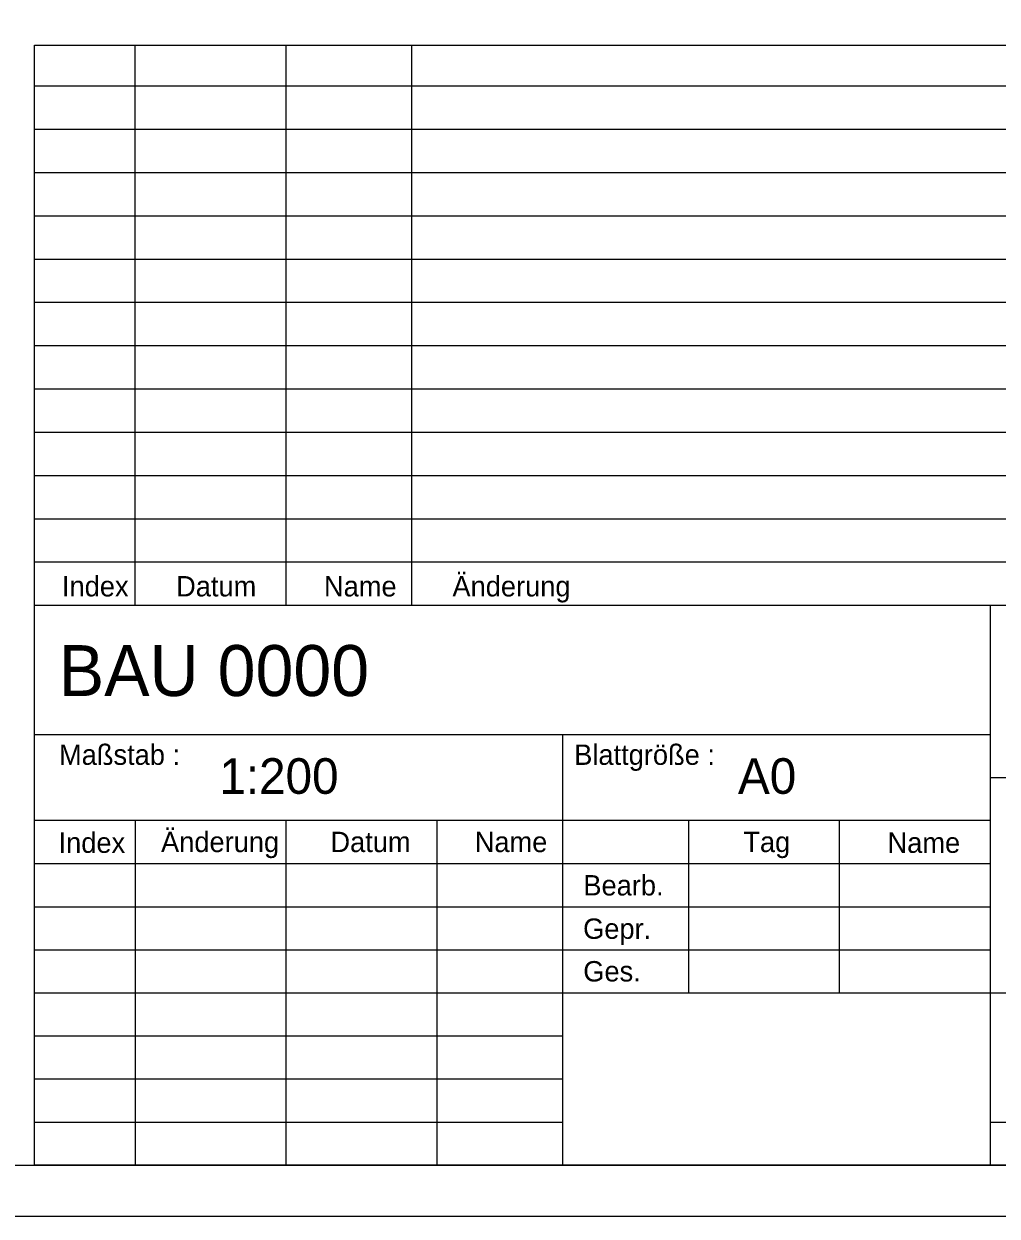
# Model space of a CAD drawing. Extents: x 0 to 238, y 0 to 168.
# Drawn here: x 201.01 to 220.13, y 0 to 23.42 of the extents above; entities that cross this region are included whole.
import ezdxf

# ---------------------------------------------------------------- set-up
doc = ezdxf.new("R2010")
doc.units = 0
doc.layers.add('90_Plankopf', color=7, linetype='Continuous')

msp = doc.modelspace()

# ---------------------------------------------------------------- linework, layer by layer
at = {"layer": '90_Plankopf'}
for p, q in [((201.224, 11.998), (201.224, 22.996)), ((201.224, 22.996), (236.8, 22.996)), ((203.2, 11.998), (203.2, 22.996)), ((206.165, 11.998), (206.165, 22.996)), ((208.636, 11.998), (208.636, 22.996)), ((201.224, 22.198), (236.8, 22.198)), ((201.224, 21.348), (236.8, 21.348)), ((201.224, 20.498), (236.8, 20.498)), ((201.224, 19.648), (236.8, 19.648)), ((201.224, 18.798), (236.8, 18.798)), ((201.224, 17.948), (236.8, 17.948)), ((201.224, 17.098), (236.8, 17.098)), ((201.224, 16.248), (236.8, 16.248)), ((201.224, 15.398), (236.8, 15.398)), ((201.224, 14.548), (236.8, 14.548)), ((201.224, 13.698), (236.8, 13.698)), ((201.224, 12.848), (236.8, 12.848)), ((201.224, 11.998), (236.8, 11.998)), ((201.224, 1), (201.224, 11.998)), ((201.224, 11.998), (236.8, 11.998)), ((220, 1), (220, 11.998)), ((201.224, 9.46), (220, 9.46)), ((211.6, 1), (211.6, 9.46)), ((220, 8.614), (236.8, 8.614)), ((201.224, 7.774), (220, 7.774)), ((203.2, 7.768), (203.2, 1)), ((206.165, 1), (206.165, 7.768)), ((209.13, 1), (209.13, 7.768)), ((214.071, 7.768), (214.071, 4.384)), ((217.036, 4.384), (217.036, 7.768)), ((201.224, 6.926), (220, 6.926)), ((201.224, 6.076), (220, 6.076)), ((201.224, 5.23), (220, 5.23)), ((201.224, 4.384), (220, 4.384)), ((201.224, 4.384), (220, 4.384)), ((211.6, 4.384), (220, 4.384)), ((220, 4.384), (236.8, 4.384)), ((211.6, 3.538), (201.224, 3.538)), ((211.6, 2.692), (201.224, 2.692)), ((201.224, 1.846), (211.6, 1.846)), ((220, 1.846), (236.8, 1.846)), ((236.8, 1), (201.224, 1)), ((201.224, 1), (211.6, 1)), ((203.56, 1), (236.8, 1)), ((203.56, 1), (236.8, 1))]:
    msp.add_line(p, q, dxfattribs=at)
for points in [[(0, 0), (237.8, 0), (237.8, 168.2), (0, 168.2)], [(5, 1), (236.8, 1), (236.8, 167.2), (5, 167.2)]]:
    msp.add_lwpolyline(points, close=True, dxfattribs=at)

# ---------------------------------------------------------------- texts
for s, height, p in [('Änderung', 0.4, (209.431, 12.171)), ('Index', 0.4, (201.761, 12.171)), ('Datum', 0.4, (204.003, 12.171)), ('Name', 0.4, (206.908, 12.171)), ('BAU 0000      ', 1, (201.698, 10.215)), ('Maßstab :', 0.4, (201.703, 8.863)), ('Blattgröße :', 0.39998, (211.823, 8.863)), ('1:200    ', 0.7, (204.852, 8.294)), ('A0       ', 0.7, (215.04, 8.294)), ('Index', 0.4, (201.694, 7.135)), ('Änderung', 0.4, (203.707, 7.15)), ('Datum', 0.4, (207.034, 7.15)), ('Name', 0.4, (209.869, 7.15)), ('Tag', 0.4, (215.145, 7.15)), ('Name', 0.4, (217.978, 7.135)), ('Bearb.', 0.4, (212.003, 6.298)), ('Gepr.', 0.4, (211.998, 5.446)), ('Ges.', 0.4, (212.001, 4.609))]:
    msp.add_text(s, height=height, dxfattribs=at).set_placement(p)

doc.saveas('drawing.dxf')
